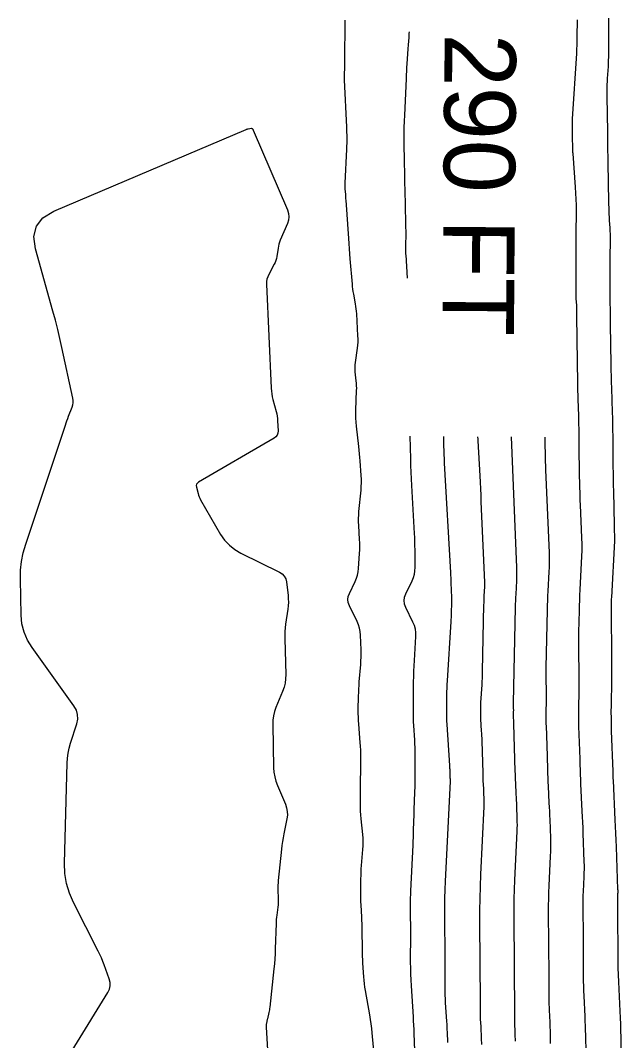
# Model space of a CAD drawing. Extents: x 1768942 to 1774819, y 723037 to 732099.
# Drawn here: x 1770468.4 to 1770518.9, y 731123.3 to 731209.1 of the extents above; entities that cross this region are included whole.
import ezdxf

# ---------------------------------------------------------------- set-up
doc = ezdxf.new("R2010")
doc.units = 0
doc.layers.add('R_Contour Annot', color=7, linetype='Continuous')
doc.layers.add('R_Contours', color=7, linetype='Continuous')

msp = doc.modelspace()

# ---------------------------------------------------------------- linework, layer by layer
at = {"layer": 'R_Contours'}
for points in [[(1770498.144, 731121.83), (1770497.954, 731123.933), (1770497.915, 731124.316), (1770497.867, 731124.698), (1770497.812, 731125.079), (1770497.748, 731125.459), (1770497.378, 731127.509), (1770497.331, 731127.794), (1770497.293, 731128.079), (1770497.262, 731128.365), (1770497.24, 731128.653), (1770497.168, 731129.804), (1770497.152, 731130.092), (1770497.14, 731130.38), (1770497.131, 731130.668), (1770497.125, 731130.957), (1770497.103, 731132.618), (1770497.099, 731132.878), (1770497.091, 731133.139), (1770497.082, 731133.399), (1770497.069, 731133.66), (1770497.014, 731134.701), (1770497.002, 731134.962), (1770496.994, 731135.222), (1770496.99, 731135.483), (1770496.99, 731135.744), (1770496.999, 731136.908), (1770497.004, 731137.189), (1770497.014, 731137.47), (1770497.03, 731137.75), (1770497.051, 731138.03), (1770497.165, 731139.362), (1770497.184, 731139.677), (1770497.189, 731139.993), (1770497.179, 731140.308), (1770497.154, 731140.623), (1770497.019, 731141.952), (1770496.991, 731142.266), (1770496.972, 731142.58), (1770496.962, 731142.894), (1770496.96, 731143.209), (1770496.968, 731144.469), (1770496.971, 731144.784), (1770496.973, 731145.099), (1770496.975, 731145.414), (1770496.978, 731145.729), (1770496.988, 731147.062), (1770496.987, 731147.389), (1770496.979, 731147.716), (1770496.963, 731148.042), (1770496.94, 731148.368), (1770496.816, 731149.912), (1770496.796, 731150.207), (1770496.783, 731150.502), (1770496.778, 731150.797), (1770496.779, 731151.092), (1770496.802, 731152.275), (1770496.81, 731152.571), (1770496.822, 731152.866), (1770496.839, 731153.161), (1770496.86, 731153.456), (1770496.978, 731154.928), (1770496.998, 731155.234), (1770497.01, 731155.541), (1770497.013, 731155.847), (1770497.008, 731156.154), (1770496.97, 731157.383), (1770496.945, 731157.686), (1770496.888, 731157.981), (1770496.8, 731158.269), (1770496.68, 731158.548), (1770496.032, 731159.867), (1770495.938, 731160.123), (1770495.906, 731160.378), (1770495.936, 731160.634), (1770496.028, 731160.891), (1770496.522, 731161.916), (1770496.632, 731162.176), (1770496.715, 731162.443), (1770496.773, 731162.716), (1770496.803, 731162.997), (1770496.881, 731164.265), (1770496.895, 731164.559), (1770496.899, 731164.853), (1770496.895, 731165.147), (1770496.882, 731165.441), (1770496.813, 731166.616), (1770496.801, 731166.91), (1770496.801, 731167.203), (1770496.812, 731167.497), (1770496.835, 731167.79), (1770497.008, 731169.593), (1770497.031, 731169.899), (1770497.042, 731170.204), (1770497.039, 731170.51), (1770497.024, 731170.815), (1770496.939, 731172.039), (1770496.916, 731172.345), (1770496.889, 731172.65), (1770496.86, 731172.955), (1770496.827, 731173.26), (1770496.634, 731174.954), (1770496.601, 731175.294), (1770496.581, 731175.635), (1770496.574, 731175.977), (1770496.58, 731176.319), (1770496.638, 731177.979), (1770496.642, 731178.176), (1770496.638, 731178.373), (1770496.627, 731178.57), (1770496.608, 731178.766), (1770496.52, 731179.55), (1770496.505, 731179.746), (1770496.501, 731179.942), (1770496.511, 731180.138), (1770496.533, 731180.333), (1770496.703, 731181.517), (1770496.734, 731181.78), (1770496.752, 731182.043), (1770496.757, 731182.307), (1770496.748, 731182.572), (1770496.642, 731184.417), (1770496.626, 731184.627), (1770496.605, 731184.836), (1770496.576, 731185.044), (1770496.542, 731185.251), (1770496.39, 731186.08), (1770496.355, 731186.287), (1770496.325, 731186.495), (1770496.3, 731186.704), (1770496.28, 731186.913), (1770496.104, 731189.045), (1770496.069, 731189.47), (1770496.036, 731189.895), (1770496.004, 731190.32), (1770495.974, 731190.746), (1770495.749, 731193.972), (1770495.741, 731194.091), (1770495.733, 731194.211), (1770495.724, 731194.331), (1770495.715, 731194.45), (1770495.681, 731194.929), (1770495.674, 731195.049), (1770495.671, 731195.168), (1770495.671, 731195.288), (1770495.675, 731195.408), (1770495.815, 731198.261), (1770495.822, 731198.415), (1770495.826, 731198.569), (1770495.829, 731198.723), (1770495.829, 731198.878), (1770495.827, 731199.495), (1770495.826, 731199.65), (1770495.823, 731199.804), (1770495.817, 731199.958), (1770495.811, 731200.112), (1770495.61, 731204.105), (1770495.605, 731204.227), (1770495.603, 731204.349), (1770495.605, 731204.471), (1770495.609, 731204.593), (1770495.632, 731205.081), (1770495.637, 731205.203), (1770495.641, 731205.325), (1770495.644, 731205.447), (1770495.646, 731205.569), (1770495.682, 731209.119)], [(1770515.934, 731122.213), (1770515.901, 731123.762), (1770515.891, 731124.149), (1770515.879, 731124.536), (1770515.865, 731124.923), (1770515.848, 731125.31), (1770515.766, 731127.053), (1770515.749, 731127.464), (1770515.736, 731127.876), (1770515.727, 731128.288), (1770515.723, 731128.7), (1770515.713, 731130.349), (1770515.71, 731130.761), (1770515.708, 731131.173), (1770515.705, 731131.586), (1770515.702, 731131.998), (1770515.685, 731134.562), (1770515.685, 731134.876), (1770515.689, 731135.19), (1770515.698, 731135.504), (1770515.711, 731135.818), (1770515.771, 731137.074), (1770515.783, 731137.388), (1770515.788, 731137.702), (1770515.787, 731138.016), (1770515.779, 731138.33), (1770515.694, 731140.735), (1770515.676, 731141.196), (1770515.658, 731141.657), (1770515.637, 731142.118), (1770515.615, 731142.578), (1770515.502, 731144.877), (1770515.491, 731145.11), (1770515.481, 731145.343), (1770515.472, 731145.577), (1770515.465, 731145.81), (1770515.437, 731146.744), (1770515.43, 731146.977), (1770515.422, 731147.211), (1770515.414, 731147.444), (1770515.406, 731147.677), (1770515.333, 731149.711), (1770515.322, 731150.087), (1770515.316, 731150.462), (1770515.314, 731150.838), (1770515.318, 731151.214), (1770515.341, 731152.717), (1770515.346, 731153.093), (1770515.348, 731153.469), (1770515.348, 731153.845), (1770515.345, 731154.221), (1770515.325, 731155.981), (1770515.322, 731156.399), (1770515.322, 731156.818), (1770515.326, 731157.236), (1770515.333, 731157.655), (1770515.368, 731159.441), (1770515.379, 731159.878), (1770515.393, 731160.315), (1770515.412, 731160.752), (1770515.434, 731161.189), (1770515.56, 731163.475), (1770515.583, 731164.001), (1770515.593, 731164.528), (1770515.59, 731165.055), (1770515.574, 731165.582), (1770515.459, 731168.347), (1770515.445, 731168.704), (1770515.433, 731169.061), (1770515.422, 731169.418), (1770515.413, 731169.774), (1770515.379, 731171.202), (1770515.372, 731171.559), (1770515.365, 731171.916), (1770515.36, 731172.273), (1770515.357, 731172.63), (1770515.342, 731174.416), (1770515.338, 731174.768), (1770515.332, 731175.12), (1770515.323, 731175.472), (1770515.312, 731175.824), (1770515.265, 731177.231), (1770515.254, 731177.583), (1770515.244, 731177.935), (1770515.237, 731178.287), (1770515.231, 731178.638), (1770515.207, 731180.345), (1770515.202, 731180.746), (1770515.197, 731181.148), (1770515.193, 731181.55), (1770515.189, 731181.951), (1770515.166, 731184.617), (1770515.163, 731184.748), (1770515.159, 731184.879), (1770515.153, 731185.01), (1770515.145, 731185.14), (1770515.109, 731185.663), (1770515.101, 731185.793), (1770515.095, 731185.924), (1770515.092, 731186.055), (1770515.091, 731186.186), (1770515.099, 731189.08), (1770515.1, 731189.578), (1770515.102, 731190.077), (1770515.104, 731190.576), (1770515.106, 731191.075), (1770515.115, 731193.07), (1770515.112, 731193.568), (1770515.1, 731194.066), (1770515.077, 731194.564), (1770515.045, 731195.062), (1770514.834, 731197.895), (1770514.827, 731197.993), (1770514.822, 731198.091), (1770514.818, 731198.189), (1770514.815, 731198.287), (1770514.806, 731198.68), (1770514.804, 731198.778), (1770514.802, 731198.877), (1770514.801, 731198.975), (1770514.799, 731199.073), (1770514.793, 731199.505), (1770514.792, 731199.61), (1770514.791, 731199.714), (1770514.789, 731199.819), (1770514.788, 731199.924), (1770514.782, 731200.381), (1770514.782, 731200.492), (1770514.784, 731200.603), (1770514.788, 731200.714), (1770514.794, 731200.825), (1770515.141, 731206.31), (1770515.161, 731206.662), (1770515.175, 731207.014), (1770515.185, 731207.366), (1770515.19, 731207.718), (1770515.198, 731209.128)], [(1770518.918, 731121.367), (1770518.871, 731123.568), (1770518.857, 731124.118), (1770518.84, 731124.668), (1770518.82, 731125.218), (1770518.796, 731125.768), (1770518.679, 731128.243), (1770518.655, 731128.828), (1770518.636, 731129.414), (1770518.624, 731129.999), (1770518.617, 731130.584), (1770518.598, 731133.83), (1770518.597, 731133.964), (1770518.596, 731134.098), (1770518.595, 731134.232), (1770518.594, 731134.366), (1770518.59, 731135.004), (1770518.59, 731135.088), (1770518.591, 731135.172), (1770518.594, 731135.256), (1770518.597, 731135.339), (1770518.613, 731135.675), (1770518.616, 731135.759), (1770518.618, 731135.843), (1770518.617, 731135.927), (1770518.615, 731136.011), (1770518.488, 731139.59), (1770518.467, 731140.16), (1770518.443, 731140.729), (1770518.418, 731141.299), (1770518.391, 731141.868), (1770518.229, 731145.159), (1770518.226, 731145.222), (1770518.223, 731145.284), (1770518.221, 731145.347), (1770518.219, 731145.41), (1770518.211, 731145.661), (1770518.209, 731145.724), (1770518.207, 731145.786), (1770518.205, 731145.849), (1770518.203, 731145.912), (1770518.08, 731149.34), (1770518.064, 731149.873), (1770518.055, 731150.407), (1770518.053, 731150.941), (1770518.058, 731151.475), (1770518.092, 731153.612), (1770518.098, 731154.146), (1770518.101, 731154.68), (1770518.101, 731155.214), (1770518.097, 731155.748), (1770518.058, 731159.214), (1770518.057, 731159.327), (1770518.057, 731159.439), (1770518.058, 731159.551), (1770518.06, 731159.663), (1770518.069, 731160.111), (1770518.072, 731160.224), (1770518.076, 731160.336), (1770518.08, 731160.448), (1770518.086, 731160.56), (1770518.349, 731165.317), (1770518.353, 731165.426), (1770518.356, 731165.536), (1770518.355, 731165.646), (1770518.352, 731165.756), (1770518.333, 731166.195), (1770518.329, 731166.305), (1770518.325, 731166.415), (1770518.322, 731166.524), (1770518.319, 731166.634), (1770518.252, 731169.495), (1770518.241, 731170.008), (1770518.232, 731170.522), (1770518.225, 731171.035), (1770518.22, 731171.549), (1770518.199, 731174.118), (1770518.193, 731174.624), (1770518.184, 731175.13), (1770518.172, 731175.636), (1770518.156, 731176.142), (1770518.087, 731178.167), (1770518.071, 731178.673), (1770518.058, 731179.179), (1770518.047, 731179.685), (1770518.039, 731180.191), (1770517.993, 731183.526), (1770517.991, 731183.663), (1770517.989, 731183.801), (1770517.988, 731183.938), (1770517.986, 731184.076), (1770517.98, 731184.824), (1770517.979, 731184.862), (1770517.978, 731184.901), (1770517.976, 731184.939), (1770517.974, 731184.978), (1770517.963, 731185.132), (1770517.961, 731185.17), (1770517.959, 731185.209), (1770517.958, 731185.248), (1770517.958, 731185.286), (1770517.97, 731189.794), (1770517.971, 731189.949), (1770517.971, 731190.104), (1770517.972, 731190.258), (1770517.972, 731190.413), (1770517.975, 731191.031), (1770517.974, 731191.185), (1770517.97, 731191.34), (1770517.964, 731191.494), (1770517.954, 731191.648), (1770517.907, 731192.275), (1770517.896, 731192.431), (1770517.888, 731192.587), (1770517.881, 731192.743), (1770517.877, 731192.899), (1770517.826, 731195.196), (1770517.817, 731195.631), (1770517.809, 731196.066), (1770517.802, 731196.501), (1770517.795, 731196.936), (1770517.769, 731198.849), (1770517.763, 731199.313), (1770517.757, 731199.776), (1770517.751, 731200.24), (1770517.745, 731200.704), (1770517.714, 731203.206), (1770517.713, 731203.46), (1770517.717, 731203.713), (1770517.726, 731203.966), (1770517.74, 731204.219), (1770517.804, 731205.23), (1770517.818, 731205.483), (1770517.829, 731205.736), (1770517.836, 731205.989), (1770517.839, 731206.242), (1770517.854, 731208.766), (1770517.857, 731209.271)], [(1770501.042, 731208.141), (1770501.034, 731207.981), (1770501.016, 731207.665), (1770500.996, 731207.348), (1770500.976, 731207.032), (1770500.954, 731206.716), (1770500.864, 731205.452), (1770500.843, 731205.136), (1770500.823, 731204.819), (1770500.806, 731204.503), (1770500.791, 731204.186), (1770500.652, 731201.136), (1770500.632, 731200.613), (1770500.619, 731200.091), (1770500.614, 731199.568), (1770500.616, 731199.045), (1770500.641, 731196.953), (1770500.648, 731196.43), (1770500.656, 731195.907), (1770500.667, 731195.384), (1770500.68, 731194.862), (1770500.751, 731192.072), (1770500.756, 731191.859), (1770500.759, 731191.647), (1770500.761, 731191.434), (1770500.76, 731191.221), (1770500.755, 731190.056), (1770500.755, 731190), (1770500.755, 731189.945), (1770500.755, 731189.889), (1770500.755, 731189.833), (1770500.754, 731189.611), (1770500.754, 731189.555), (1770500.756, 731189.5), (1770500.758, 731189.444), (1770500.761, 731189.389), (1770500.899, 731187.413)], [(1770469.938, 731117.942), (1770475.719, 731127.348), (1770475.849, 731127.619), (1770475.912, 731127.898), (1770475.906, 731128.183), (1770475.833, 731128.475), (1770475.402, 731129.658), (1770475.29, 731129.951), (1770475.169, 731130.241), (1770475.04, 731130.527), (1770474.902, 731130.81), (1770472.824, 731134.907), (1770472.482, 731135.695), (1770472.244, 731136.507), (1770472.111, 731137.342), (1770472.082, 731138.2), (1770472.305, 731146.628), (1770472.331, 731147.053), (1770472.387, 731147.473), (1770472.472, 731147.889), (1770472.587, 731148.299), (1770473.105, 731149.93), (1770473.187, 731150.33), (1770473.174, 731150.715), (1770473.067, 731151.085), (1770472.864, 731151.44), (1770469.338, 731156.343), (1770468.951, 731156.974), (1770468.669, 731157.64), (1770468.494, 731158.342), (1770468.425, 731159.08), (1770468.362, 731162.1), (1770468.378, 731162.85), (1770468.457, 731163.591), (1770468.6, 731164.321), (1770468.807, 731165.043), (1770472.141, 731175.046), (1770472.206, 731175.238), (1770472.273, 731175.428), (1770472.343, 731175.618), (1770472.415, 731175.807), (1770472.708, 731176.561), (1770472.767, 731176.751), (1770472.797, 731176.943), (1770472.798, 731177.137), (1770472.77, 731177.334), (1770471.858, 731181.57), (1770471.686, 731182.34), (1770471.502, 731183.108), (1770471.307, 731183.873), (1770471.101, 731184.635), (1770469.639, 731189.873), (1770469.499, 731190.915), (1770469.706, 731191.791), (1770470.261, 731192.5), (1770471.163, 731193.041), (1770487.335, 731199.924), (1770487.381, 731199.942), (1770487.428, 731199.957), (1770487.476, 731199.969), (1770487.525, 731199.979), (1770487.798, 731200.023), (1770487.809, 731200.024), (1770487.819, 731200.022), (1770487.828, 731200.017), (1770487.836, 731200.01), (1770487.868, 731199.975), (1770487.876, 731199.967), (1770487.883, 731199.959), (1770487.889, 731199.95), (1770487.895, 731199.941), (1770487.919, 731199.904), (1770487.924, 731199.895), (1770487.93, 731199.885), (1770487.935, 731199.876), (1770487.939, 731199.866), (1770490.812, 731193.149), (1770490.905, 731192.862), (1770490.936, 731192.575), (1770490.905, 731192.287), (1770490.814, 731192), (1770490.218, 731190.597), (1770490.155, 731190.434), (1770490.102, 731190.269), (1770490.06, 731190.101), (1770490.029, 731189.929), (1770489.925, 731189.238), (1770489.892, 731189.068), (1770489.845, 731188.902), (1770489.783, 731188.741), (1770489.708, 731188.585), (1770489.249, 731187.733), (1770489.159, 731187.536), (1770489.098, 731187.333), (1770489.065, 731187.124), (1770489.06, 731186.908), (1770489.451, 731178.154), (1770489.469, 731177.914), (1770489.499, 731177.677), (1770489.542, 731177.441), (1770489.599, 731177.208), (1770489.869, 731176.208), (1770489.917, 731176.009), (1770489.954, 731175.809), (1770489.979, 731175.606), (1770489.994, 731175.402), (1770490.029, 731174.583), (1770490.015, 731174.39), (1770489.954, 731174.224), (1770489.847, 731174.082), (1770489.693, 731173.966), (1770483.345, 731170.262), (1770483.242, 731170.182), (1770483.178, 731170.086), (1770483.153, 731169.974), (1770483.166, 731169.844), (1770483.298, 731169.294), (1770483.336, 731169.158), (1770483.383, 731169.027), (1770483.44, 731168.899), (1770483.506, 731168.775), (1770485.202, 731165.867), (1770485.538, 731165.373), (1770485.934, 731164.945), (1770486.391, 731164.581), (1770486.907, 731164.281), (1770490.152, 731162.694), (1770490.382, 731162.547), (1770490.556, 731162.361), (1770490.673, 731162.135), (1770490.734, 731161.869), (1770490.865, 731160.726), (1770490.889, 731160.44), (1770490.894, 731160.155), (1770490.88, 731159.87), (1770490.848, 731159.585), (1770490.663, 731158.308), (1770490.625, 731158), (1770490.601, 731157.691), (1770490.589, 731157.381), (1770490.591, 731157.071), (1770490.672, 731154.074), (1770490.663, 731153.711), (1770490.617, 731153.354), (1770490.534, 731153.004), (1770490.413, 731152.66), (1770489.855, 731151.301), (1770489.734, 731150.958), (1770489.65, 731150.608), (1770489.602, 731150.251), (1770489.59, 731149.887), (1770489.659, 731146.242), (1770489.684, 731145.854), (1770489.746, 731145.474), (1770489.845, 731145.102), (1770489.98, 731144.738), (1770490.645, 731143.171), (1770490.748, 731142.87), (1770490.803, 731142.565), (1770490.811, 731142.254), (1770490.77, 731141.939), (1770490.513, 731140.669), (1770490.452, 731140.351), (1770490.4, 731140.032), (1770490.355, 731139.711), (1770490.318, 731139.389), (1770490.048, 731136.743), (1770490.032, 731136.557), (1770490.022, 731136.37), (1770490.019, 731136.183), (1770490.022, 731135.996), (1770490.049, 731135.222), (1770490.051, 731135.047), (1770490.045, 731134.873), (1770490.032, 731134.7), (1770490.012, 731134.526), (1770489.915, 731133.834), (1770489.894, 731133.661), (1770489.876, 731133.487), (1770489.864, 731133.313), (1770489.856, 731133.139), (1770489.792, 731130.997), (1770489.775, 731130.582), (1770489.75, 731130.167), (1770489.718, 731129.753), (1770489.677, 731129.34), (1770489.327, 731126.109), (1770489.313, 731125.997), (1770489.296, 731125.885), (1770489.276, 731125.774), (1770489.253, 731125.663), (1770489.131, 731125.115), (1770489.118, 731125.058), (1770489.106, 731125), (1770489.094, 731124.942), (1770489.083, 731124.885), (1770489.038, 731124.653), (1770489.029, 731124.596), (1770489.023, 731124.537), (1770489.021, 731124.479), (1770489.023, 731124.42), (1770489.256, 731120.619)], [(1770501.123, 731174.123), (1770501.165, 731172.218), (1770501.18, 731171.659), (1770501.199, 731171.101), (1770501.223, 731170.543), (1770501.252, 731169.984), (1770501.478, 731165.946), (1770501.495, 731165.6), (1770501.508, 731165.254), (1770501.516, 731164.908), (1770501.519, 731164.562), (1770501.526, 731163.092), (1770501.51, 731162.791), (1770501.462, 731162.499), (1770501.38, 731162.213), (1770501.265, 731161.936), (1770500.737, 731160.84), (1770500.639, 731160.566), (1770500.607, 731160.292), (1770500.641, 731160.019), (1770500.742, 731159.746), (1770501.345, 731158.517), (1770501.47, 731158.217), (1770501.553, 731157.909), (1770501.594, 731157.592), (1770501.594, 731157.268), (1770501.465, 731155.252), (1770501.44, 731154.806), (1770501.42, 731154.36), (1770501.407, 731153.914), (1770501.4, 731153.467), (1770501.378, 731151.03), (1770501.379, 731150.721), (1770501.384, 731150.412), (1770501.396, 731150.103), (1770501.413, 731149.795), (1770501.494, 731148.562), (1770501.512, 731148.254), (1770501.525, 731147.945), (1770501.533, 731147.636), (1770501.536, 731147.327), (1770501.538, 731145.93), (1770501.537, 731145.629), (1770501.533, 731145.327), (1770501.526, 731145.026), (1770501.517, 731144.725), (1770501.473, 731143.521), (1770501.463, 731143.22), (1770501.453, 731142.919), (1770501.444, 731142.618), (1770501.435, 731142.317), (1770501.401, 731141.01), (1770501.391, 731140.692), (1770501.38, 731140.374), (1770501.368, 731140.056), (1770501.353, 731139.738), (1770501.168, 731135.886), (1770501.156, 731135.585), (1770501.147, 731135.285), (1770501.143, 731134.984), (1770501.143, 731134.684), (1770501.151, 731133.481), (1770501.153, 731133.18), (1770501.154, 731132.88), (1770501.155, 731132.579), (1770501.154, 731132.278), (1770501.15, 731129.886), (1770501.154, 731129.387), (1770501.165, 731128.889), (1770501.185, 731128.39), (1770501.212, 731127.892), (1770501.379, 731125.295), (1770501.4, 731124.94), (1770501.42, 731124.585), (1770501.437, 731124.23), (1770501.452, 731123.875), (1770501.509, 731122.455)], [(1770504.304, 731123.129), (1770504.269, 731124.008), (1770504.26, 731124.227), (1770504.249, 731124.447), (1770504.237, 731124.666), (1770504.224, 731124.886), (1770504.121, 731126.493), (1770504.104, 731126.801), (1770504.092, 731127.11), (1770504.085, 731127.418), (1770504.083, 731127.727), (1770504.085, 731128.962), (1770504.085, 731129.271), (1770504.085, 731129.579), (1770504.083, 731129.888), (1770504.082, 731130.197), (1770504.057, 731133.844), (1770504.057, 731134.555), (1770504.067, 731135.266), (1770504.086, 731135.976), (1770504.116, 731136.686), (1770504.519, 731145.08), (1770504.52, 731145.108), (1770504.521, 731145.137), (1770504.521, 731145.166), (1770504.52, 731145.194), (1770504.516, 731145.313), (1770504.515, 731145.339), (1770504.514, 731145.366), (1770504.512, 731145.393), (1770504.511, 731145.42), (1770504.506, 731145.526), (1770504.505, 731145.553), (1770504.504, 731145.58), (1770504.503, 731145.606), (1770504.502, 731145.633), (1770504.488, 731146.084), (1770504.485, 731146.168), (1770504.482, 731146.252), (1770504.477, 731146.335), (1770504.472, 731146.419), (1770504.246, 731149.871), (1770504.229, 731150.176), (1770504.217, 731150.481), (1770504.211, 731150.787), (1770504.211, 731151.092), (1770504.222, 731152.314), (1770504.227, 731152.62), (1770504.236, 731152.925), (1770504.249, 731153.23), (1770504.267, 731153.535), (1770504.586, 731158.537), (1770504.596, 731158.707), (1770504.604, 731158.876), (1770504.61, 731159.046), (1770504.614, 731159.215), (1770504.633, 731160.168), (1770504.634, 731160.201), (1770504.635, 731160.234), (1770504.636, 731160.266), (1770504.638, 731160.299), (1770504.645, 731160.43), (1770504.647, 731160.463), (1770504.647, 731160.496), (1770504.647, 731160.528), (1770504.646, 731160.561), (1770504.595, 731161.786), (1770504.586, 731162.001), (1770504.575, 731162.216), (1770504.565, 731162.431), (1770504.553, 731162.646), (1770504.038, 731171.865), (1770504.019, 731172.218), (1770504.004, 731172.571), (1770503.992, 731172.924), (1770503.983, 731173.277), (1770503.964, 731174.104)], [(1770506.808, 731174.084), (1770506.809, 731174.04), (1770506.815, 731173.893), (1770506.823, 731173.745), (1770506.988, 731170.792), (1770507.017, 731170.251), (1770507.045, 731169.709), (1770507.07, 731169.168), (1770507.094, 731168.626), (1770507.378, 731161.816), (1770507.383, 731161.66), (1770507.384, 731161.504), (1770507.381, 731161.347), (1770507.374, 731161.191), (1770507.339, 731160.566), (1770507.332, 731160.41), (1770507.325, 731160.254), (1770507.32, 731160.098), (1770507.316, 731159.941), (1770507.205, 731154.352), (1770507.197, 731154.066), (1770507.187, 731153.779), (1770507.173, 731153.493), (1770507.157, 731153.207), (1770507.062, 731151.725), (1770507.055, 731151.608), (1770507.05, 731151.49), (1770507.047, 731151.373), (1770507.045, 731151.255), (1770507.041, 731150.785), (1770507.041, 731150.668), (1770507.043, 731150.55), (1770507.047, 731150.433), (1770507.054, 731150.316), (1770507.119, 731149.33), (1770507.131, 731149.127), (1770507.142, 731148.923), (1770507.151, 731148.72), (1770507.158, 731148.516), (1770507.239, 731145.791), (1770507.243, 731145.656), (1770507.248, 731145.521), (1770507.254, 731145.385), (1770507.26, 731145.25), (1770507.287, 731144.709), (1770507.294, 731144.574), (1770507.3, 731144.439), (1770507.305, 731144.303), (1770507.31, 731144.168), (1770507.332, 731143.568), (1770507.335, 731143.423), (1770507.336, 731143.278), (1770507.333, 731143.133), (1770507.328, 731142.988), (1770507.052, 731137.255), (1770507.011, 731136.251), (1770506.983, 731135.247), (1770506.969, 731134.242), (1770506.969, 731133.237), (1770507.015, 731126.516), (1770507.015, 731126.397), (1770507.016, 731126.279), (1770507.016, 731126.16), (1770507.016, 731126.042), (1770507.015, 731125.568), (1770507.016, 731125.449), (1770507.019, 731125.331), (1770507.023, 731125.212), (1770507.03, 731125.094), (1770507.069, 731124.477), (1770507.074, 731124.393), (1770507.079, 731124.309), (1770507.083, 731124.224), (1770507.087, 731124.14), (1770507.1, 731123.802), (1770507.103, 731123.718), (1770507.107, 731123.634), (1770507.11, 731123.549), (1770507.112, 731123.465), (1770507.13, 731122.949)], [(1770509.994, 731123.248), (1770509.991, 731123.314), (1770509.988, 731123.381), (1770509.975, 731123.658), (1770509.972, 731123.72), (1770509.97, 731123.781), (1770509.968, 731123.842), (1770509.967, 731123.904), (1770509.962, 731124.149), (1770509.96, 731124.211), (1770509.958, 731124.272), (1770509.956, 731124.333), (1770509.953, 731124.395), (1770509.94, 731124.671), (1770509.937, 731124.736), (1770509.935, 731124.802), (1770509.934, 731124.867), (1770509.933, 731124.932), (1770509.932, 731125.194), (1770509.931, 731125.324), (1770509.93, 731125.455), (1770509.875, 731133.679), (1770509.875, 731134.453), (1770509.885, 731135.228), (1770509.907, 731136.002), (1770509.938, 731136.776), (1770510.137, 731140.897), (1770510.146, 731141.158), (1770510.151, 731141.419), (1770510.15, 731141.681), (1770510.143, 731141.942), (1770510.105, 731143.024), (1770510.096, 731143.268), (1770510.086, 731143.511), (1770510.075, 731143.755), (1770510.063, 731143.999), (1770510.015, 731144.974), (1770510.004, 731145.218), (1770509.993, 731145.462), (1770509.984, 731145.706), (1770509.976, 731145.949), (1770509.857, 731149.931), (1770509.855, 731149.995), (1770509.853, 731150.059), (1770509.851, 731150.123), (1770509.849, 731150.188), (1770509.839, 731150.454), (1770509.838, 731150.513), (1770509.837, 731150.573), (1770509.836, 731150.632), (1770509.837, 731150.691), (1770509.841, 731150.929), (1770509.841, 731150.988), (1770509.842, 731151.047), (1770509.842, 731151.107), (1770509.841, 731151.166), (1770509.838, 731151.444), (1770509.838, 731151.51), (1770509.838, 731151.576), (1770509.838, 731151.642), (1770509.839, 731151.708), (1770509.999, 731159.714), (1770510.006, 731159.994), (1770510.015, 731160.274), (1770510.027, 731160.554), (1770510.041, 731160.834), (1770510.103, 731161.952), (1770510.115, 731162.232), (1770510.12, 731162.512), (1770510.119, 731162.792), (1770510.11, 731163.071), (1770509.651, 731174.064)], [(1770512.95, 731123.058), (1770512.931, 731123.955), (1770512.926, 731124.18), (1770512.919, 731124.404), (1770512.91, 731124.628), (1770512.901, 731124.852), (1770512.853, 731125.862), (1770512.843, 731126.1), (1770512.836, 731126.339), (1770512.831, 731126.578), (1770512.828, 731126.816), (1770512.822, 731127.771), (1770512.821, 731128.01), (1770512.819, 731128.249), (1770512.818, 731128.488), (1770512.816, 731128.727), (1770512.78, 731134.12), (1770512.78, 731134.665), (1770512.787, 731135.209), (1770512.802, 731135.753), (1770512.825, 731136.297), (1770512.945, 731138.805), (1770512.959, 731139.183), (1770512.966, 731139.561), (1770512.964, 731139.938), (1770512.955, 731140.316), (1770512.899, 731141.879), (1770512.886, 731142.232), (1770512.872, 731142.584), (1770512.856, 731142.936), (1770512.839, 731143.289), (1770512.77, 731144.698), (1770512.753, 731145.05), (1770512.738, 731145.403), (1770512.725, 731145.755), (1770512.714, 731146.108), (1770512.652, 731148.164), (1770512.645, 731148.4), (1770512.637, 731148.635), (1770512.629, 731148.87), (1770512.621, 731149.106), (1770512.586, 731150.083), (1770512.58, 731150.3), (1770512.576, 731150.518), (1770512.575, 731150.735), (1770512.577, 731150.953), (1770512.591, 731151.823), (1770512.594, 731152.041), (1770512.595, 731152.258), (1770512.595, 731152.476), (1770512.593, 731152.693), (1770512.582, 731153.712), (1770512.58, 731153.955), (1770512.58, 731154.197), (1770512.582, 731154.439), (1770512.586, 731154.682), (1770512.682, 731159.488), (1770512.692, 731159.891), (1770512.705, 731160.295), (1770512.722, 731160.698), (1770512.742, 731161.101), (1770512.832, 731162.714), (1770512.849, 731163.117), (1770512.856, 731163.52), (1770512.854, 731163.923), (1770512.842, 731164.327), (1770512.551, 731171.306), (1770512.543, 731171.506), (1770512.536, 731171.707), (1770512.53, 731171.907), (1770512.525, 731172.108), (1770512.506, 731172.909), (1770512.502, 731173.11), (1770512.498, 731173.31), (1770512.496, 731173.511), (1770512.494, 731173.711), (1770512.491, 731174.045)]]:
    msp.add_lwpolyline(points, dxfattribs=at)

# ---------------------------------------------------------------- texts
at = {"layer": 'R_Contour Annot'}
msp.add_text('290 FT', height=6, rotation=269.6044, dxfattribs=at).set_placement((1770504.041, 731208.002))

doc.saveas('drawing.dxf')
